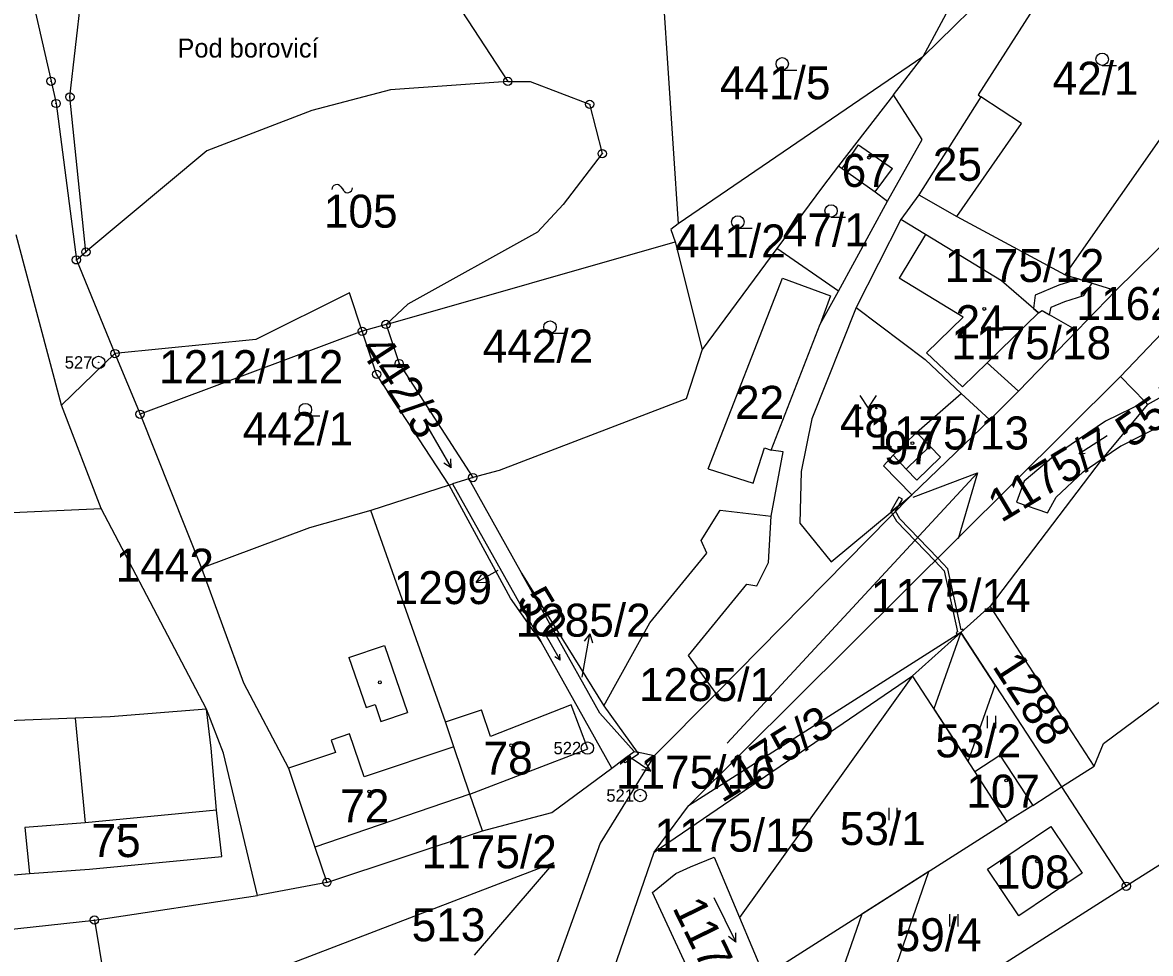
# Model space of a CAD drawing. Extents: x -564516 to -563466, y -1163913 to -1163170.
# Drawn here: x -564413.8 to -564277.2, y -1163494.9 to -1163382.1 of the extents above; entities that cross this region are included whole.
import ezdxf

# ---------------------------------------------------------------- set-up
doc = ezdxf.new("R2010")
doc.units = 0
for name, color, linetype in [('_ZOV', 7, 'Continuous'), ('Hranice parcel', 7, 'Continuous'), ('Parcelní čísla', 7, 'Continuous'), ('Pop  PČ popisy', 7, 'Continuous'), ('Vnitřní kresba', 7, 'Continuous'), ('Věcná břemena k části', 7, 'Continuous'), ('Značky bodu BP', 7, 'Continuous'), ('Značky budov', 7, 'Continuous'), ('Značky kultur', 7, 'Continuous')]:
    doc.layers.add(name, color=color, linetype=linetype)

msp = doc.modelspace()

# ---------------------------------------------------------------- linework, layer by layer
at = {"layer": '_ZOV'}
msp.add_line((-564328.48, -1163469.41), (-564298.18, -1163436.66), dxfattribs=at)
msp.add_lwpolyline([(-564305.96, -1163439.6), (-564298.18, -1163436.66), (-564300.5, -1163444.65)], dxfattribs=at)
at = {"layer": 'Hranice parcel'}
for p, q in [((-564287.56, -1163412.69), (-564255.92, -1163367.46)), ((-564299.02, -1163375.58), (-564304.77, -1163386.26)), ((-564336.38, -1163376.93), (-564334.4, -1163406.5)), ((-564304.77, -1163386.26), (-564334.4, -1163406.5)), ((-564308.34, -1163390.89), (-564304.77, -1163386.26)), ((-564308.34, -1163390.89), (-564315, -1163399.49)), ((-564297.75, -1163391.1), (-564305.26, -1163403.01)), ((-564281.4, -1163414.57), (-564257.3, -1163390.75)), ((-564314.98, -1163414.67), (-564309.04, -1163403.77)), ((-564305.26, -1163403.01), (-564307.45, -1163405.97)), ((-564305.26, -1163403.01), (-564300.68, -1163405.61)), ((-564307.45, -1163405.97), (-564312.84, -1163416.65)), ((-564300.68, -1163405.61), (-564287.56, -1163412.69)), ((-564409.08, -1163428.48), (-564414.56, -1163407.85)), ((-564369.77, -1163418.69), (-564334.77, -1163408.7)), ((-564334.77, -1163408.7), (-564331.48, -1163421.73)), ((-564322.46, -1163409.5), (-564331.48, -1163421.73)), ((-564314.98, -1163414.67), (-564322.46, -1163409.5)), ((-564407.26, -1163410.87), (-564406.11, -1163409.91)), ((-564407.26, -1163410.87), (-564402.59, -1163422.22)), ((-564287.56, -1163412.69), (-564281.4, -1163414.57)), ((-564269.44, -1163412.98), (-564280.83, -1163424.99)), ((-564372.65, -1163419.52), (-564374.19, -1163414.85)), ((-564281.4, -1163414.57), (-564286.09, -1163419.43)), ((-564367.13, -1163416.23), (-564369.77, -1163418.69)), ((-564369.77, -1163418.69), (-564372.65, -1163419.52)), ((-564372.65, -1163419.52), (-564399.56, -1163429.57)), ((-564286.09, -1163419.43), (-564293.19, -1163426.78)), ((-564409.08, -1163428.48), (-564402.59, -1163422.22)), ((-564402.59, -1163422.22), (-564399.56, -1163429.57)), ((-564333.17, -1163477.01), (-564280.83, -1163424.99)), ((-564280.83, -1163424.99), (-564277.87, -1163428.08)), ((-564305.53, -1163431.79), (-564300.13, -1163427.07)), ((-564300.13, -1163427.07), (-564296.65, -1163430.25)), ((-564296.65, -1163430.25), (-564293.19, -1163426.78)), ((-564277.59, -1163428.4), (-564275.38, -1163427.19)), ((-564404.27, -1163440.99), (-564409.08, -1163428.48)), ((-564277.59, -1163428.4), (-564283.08, -1163434.99)), ((-564277.87, -1163428.08), (-564282.66, -1163430.41)), ((-564277.87, -1163428.08), (-564277.59, -1163428.4)), ((-564399.56, -1163429.57), (-564392.13, -1163448.22)), ((-564296.65, -1163430.25), (-564306.13, -1163439.34)), ((-564305.53, -1163431.79), (-564308.38, -1163434.53)), ((-564280.8, -1163433.44), (-564283.08, -1163434.99)), ((-564283.08, -1163434.99), (-564296.64, -1163452.83)), ((-564285.36, -1163436.53), (-564283.08, -1163434.99)), ((-564362.14, -1163438.16), (-564371.62, -1163441.24)), ((-564362.14, -1163438.16), (-564361.71, -1163438.02)), ((-564359.75, -1163437.39), (-564361.71, -1163438.02)), ((-564361.71, -1163438.02), (-564351.01, -1163457.13)), ((-564359.27, -1163437.24), (-564359.75, -1163437.39)), ((-564359.75, -1163437.39), (-564353.36, -1163448.83)), ((-564306.13, -1163439.34), (-564329.81, -1163463.41)), ((-564463.39, -1163443.69), (-564404.27, -1163440.99)), ((-564391.49, -1163465.3), (-564404.27, -1163440.99)), ((-564353.36, -1163448.83), (-564343.41, -1163464.9)), ((-564296.64, -1163452.83), (-564300.18, -1163456.01)), ((-564284.03, -1163472.2), (-564296.64, -1163452.83)), ((-564300.18, -1163456.01), (-564333.17, -1163477.01)), ((-564306.04, -1163461.28), (-564300.18, -1163456.01)), ((-564300.18, -1163456.01), (-564287.99, -1163474.72)), ((-564342.44, -1163472.44), (-564351.01, -1163457.13)), ((-564337.31, -1163482.64), (-564306.04, -1163461.28)), ((-564306.04, -1163461.28), (-564326.97, -1163490.55)), ((-564298.48, -1163472.87), (-564306.04, -1163461.28)), ((-564282.89, -1163469.47), (-564271.83, -1163461.21)), ((-564329.81, -1163463.41), (-564337.3, -1163470.94)), ((-564343.41, -1163464.9), (-564339.38, -1163470.49)), ((-564284.03, -1163472.2), (-564282.89, -1163469.47)), ((-564341.11, -1163471.45), (-564339.72, -1163470.42)), ((-564339.2, -1163470.74), (-564340.83, -1163471.82)), ((-564339.72, -1163470.42), (-564339.38, -1163470.49)), ((-564337.3, -1163470.94), (-564339.38, -1163470.49)), ((-564339.38, -1163470.49), (-564339.2, -1163470.74)), ((-564342.44, -1163472.44), (-564341.11, -1163471.45)), ((-564340.83, -1163471.82), (-564341.11, -1163471.45)), ((-564287.99, -1163474.72), (-564284.03, -1163472.2)), ((-564294.55, -1163478.9), (-564298.48, -1163472.87)), ((-564291.48, -1163476.95), (-564287.99, -1163474.72)), ((-564287.99, -1163474.72), (-564280.15, -1163486.75)), ((-564337.31, -1163482.64), (-564333.17, -1163477.01)), ((-564291.48, -1163476.95), (-564294.55, -1163478.9)), ((-564323.98, -1163497.65), (-564294.55, -1163478.9)), ((-564376.94, -1163486.28), (-564358.11, -1163480.05)), ((-564347.82, -1163513.14), (-564337.31, -1163482.64)), ((-564330.06, -1163483.22), (-564326.97, -1163490.55)), ((-564274.36, -1163483.08), (-564280.15, -1163486.75)), ((-564412.93, -1163485.19), (-564405.68, -1163484.7)), ((-564429, -1163486.59), (-564412.93, -1163485.19)), ((-564376.94, -1163486.28), (-564385.35, -1163487.87)), ((-564280.15, -1163486.75), (-564304.67, -1163502.3)), ((-564405.08, -1163490.85), (-564385.35, -1163487.87)), ((-564332.5, -1163498.27), (-564337.51, -1163487.49)), ((-564405.08, -1163490.85), (-564403.85, -1163498.15)), ((-564326.97, -1163490.55), (-564323.98, -1163497.65))]:
    msp.add_line(p, q, dxfattribs=at)
for points in [[(-564304.77, -1163386.26), (-564295.23, -1163376.85), (-564283.56, -1163360.04), (-564247.75, -1163294.75)], [(-564375.89, -1163347.26), (-564386.66, -1163348.36), (-564392.67, -1163348.57), (-564397.72, -1163348.74), (-564404.66, -1163348.94), (-564419.03, -1163351.27), (-564410.33, -1163389.23), (-564409.72, -1163391.93), (-564407.26, -1163410.87)], [(-564406.11, -1163409.91), (-564408.05, -1163391.13), (-564406.67, -1163379.14), (-564401.67, -1163361.22), (-564394.92, -1163353.8), (-564383.29, -1163353.05), (-564374.57, -1163359.32), (-564355.03, -1163389.25)], [(-564274.65, -1163354.2), (-564298.1, -1163390.87), (-564297.75, -1163391.1)], [(-564355.03, -1163389.25), (-564369.22, -1163390.28), (-564378.74, -1163392.79), (-564391.47, -1163397.67), (-564406.11, -1163409.91)], [(-564355.03, -1163389.25), (-564352.34, -1163389.27), (-564345.12, -1163392.02), (-564343.6, -1163398), (-564348.33, -1163404.16), (-564351.45, -1163407.53), (-564367.13, -1163416.23)], [(-564309.04, -1163403.77), (-564304.87, -1163396.28), (-564308.34, -1163390.89)], [(-564300.68, -1163405.61), (-564292.84, -1163394.33), (-564297.75, -1163391.1)], [(-564315, -1163399.49), (-564316.94, -1163402.01), (-564322.46, -1163409.5)], [(-564315, -1163399.49), (-564314.55, -1163399.81), (-564310.57, -1163402.64), (-564309.04, -1163403.77)], [(-564334.4, -1163406.5), (-564335.29, -1163407.18), (-564334.77, -1163408.7)], [(-564290.77, -1163417.28), (-564295.26, -1163413.39), (-564304.44, -1163407.8), (-564307.45, -1163405.97)], [(-564374.19, -1163414.85), (-564385.53, -1163420.52), (-564402.59, -1163422.22)], [(-564323.13, -1163441.93), (-564321.68, -1163434.14), (-564323.16, -1163433.91), (-564317.21, -1163418.65), (-564314.98, -1163414.67)], [(-564312.84, -1163416.65), (-564318.21, -1163430.13), (-564319.52, -1163436.5), (-564319.69, -1163442.75), (-564315.89, -1163447.44), (-564306.13, -1163439.34)], [(-564312.84, -1163416.65), (-564304.48, -1163422.93), (-564300.13, -1163427.07)], [(-564293.19, -1163426.78), (-564296.98, -1163423.34), (-564290.77, -1163417.28)], [(-564290.77, -1163417.28), (-564290.33, -1163417), (-564286.09, -1163419.43)], [(-564369.77, -1163418.69), (-564368.18, -1163423.43), (-564359.27, -1163437.24)], [(-564362.14, -1163438.16), (-564370.91, -1163424.73), (-564372.65, -1163419.52)], [(-564331.48, -1163421.73), (-564333.44, -1163427.72), (-564356.08, -1163436.39), (-564359.27, -1163437.24)], [(-564266.24, -1163424.28), (-564275.15, -1163430.58), (-564280.8, -1163433.44)], [(-564282.66, -1163430.41), (-564288.94, -1163434.68), (-564292.52, -1163437.68), (-564293.42, -1163440.24), (-564289.69, -1163441.52), (-564288.64, -1163439.6), (-564285.36, -1163436.53)], [(-564308.38, -1163434.53), (-564306.81, -1163436.21), (-564305.52, -1163437.55), (-564302.65, -1163434.78), (-564303.94, -1163433.44), (-564305.53, -1163431.79)], [(-564306.13, -1163439.34), (-564309.54, -1163435.83), (-564308.38, -1163434.53)], [(-564351.01, -1163457.13), (-564354.7, -1163451.84), (-564362.14, -1163438.16)], [(-564371.62, -1163441.24), (-564379.02, -1163443.34), (-564392.13, -1163448.22)], [(-564358.11, -1163480.05), (-564359.63, -1163475.6), (-564361.55, -1163469.86), (-564362.57, -1163466.83), (-564371.62, -1163441.24)], [(-564343.41, -1163464.9), (-564337.83, -1163454.86), (-564330.94, -1163446.42), (-564331.62, -1163444.86), (-564329.33, -1163441.19), (-564323.13, -1163441.93)], [(-564329.81, -1163463.41), (-564333.15, -1163458.81), (-564326.08, -1163450.15), (-564324.88, -1163450.36), (-564323.47, -1163447.53), (-564323.13, -1163441.93)], [(-564392.13, -1163448.22), (-564387.04, -1163462.09), (-564381.6, -1163472.46), (-564378.4, -1163482.02), (-564376.94, -1163486.28)], [(-564339.72, -1163470.42), (-564343.9, -1163465.78), (-564353.36, -1163448.83)], [(-564391.49, -1163465.3), (-564403.17, -1163466.24), (-564407.43, -1163466.4)], [(-564405.68, -1163484.7), (-564389.65, -1163483.16), (-564390.28, -1163477.54), (-564390.95, -1163470.01), (-564391.49, -1163465.3)], [(-564385.35, -1163487.87), (-564389.44, -1163470.62), (-564391.49, -1163465.3)], [(-564407.43, -1163466.4), (-564414.53, -1163466.68), (-564430.16, -1163467.25)], [(-564407.43, -1163466.4), (-564406.22, -1163479.07), (-564413.51, -1163479.62), (-564412.93, -1163485.19)], [(-564337.3, -1163470.94), (-564343.85, -1163481.54), (-564352.25, -1163504.82), (-564360.15, -1163525.07)], [(-564298.48, -1163472.87), (-564295.46, -1163470.87), (-564291.48, -1163476.95)], [(-564358.11, -1163480.05), (-564349.68, -1163477.81), (-564342.44, -1163472.44)], [(-564289.29, -1163479.52), (-564285.5, -1163485.18), (-564293.17, -1163490.33), (-564296.94, -1163484.67), (-564289.29, -1163479.52)], [(-564337.51, -1163487.49), (-564334.69, -1163485.22), (-564332.93, -1163484.41), (-564330.06, -1163483.22)], [(-564359.05, -1163495.11), (-564349.44, -1163483.92), (-564380.93, -1163495.99)], [(-564516.35, -1163486.11), (-564490.44, -1163494.01), (-564475.97, -1163496.01), (-564456, -1163496.4), (-564405.08, -1163490.85)]]:
    msp.add_lwpolyline(points, dxfattribs=at)
at = {"layer": 'Pop  PČ popisy'}
for p, q in [((-564356.22, -1163448.5), (-564358.85, -1163449.96)), ((-564358.85, -1163449.96), (-564358.21, -1163449.03)), ((-564358.85, -1163449.96), (-564357.73, -1163449.91)), ((-564345.11, -1163456.19), (-564345.78, -1163457.08)), ((-564345.63, -1163459.14), (-564345.11, -1163456.19)), ((-564345.11, -1163456.19), (-564344.79, -1163457.26)), ((-564346.04, -1163461.41), (-564345.63, -1163459.14)), ((-564340.2, -1163471.13), (-564337.71, -1163472.81)), ((-564337.71, -1163472.81), (-564338.26, -1163471.83)), ((-564337.71, -1163472.81), (-564338.82, -1163472.66))]:
    msp.add_line(p, q, dxfattribs=at)
at = {"layer": 'Vnitřní kresba'}
for p, q in [((-564314.55, -1163399.81), (-564312.55, -1163396.94)), ((-564312.55, -1163396.94), (-564308.47, -1163399.79)), ((-564310.57, -1163402.64), (-564308.47, -1163399.79)), ((-564304.44, -1163407.8), (-564307.66, -1163413.1)), ((-564330.78, -1163436.17), (-564321.79, -1163413.09)), ((-564321.79, -1163413.09), (-564315.96, -1163415.21)), ((-564299.91, -1163417.82), (-564307.66, -1163413.1)), ((-564315.96, -1163415.21), (-564317.21, -1163418.65)), ((-564304.32, -1163422.12), (-564299.91, -1163417.82)), ((-564304.32, -1163422.12), (-564299.97, -1163426.26)), ((-564299.97, -1163426.26), (-564296.98, -1163423.34)), ((-564325.31, -1163437.92), (-564323.94, -1163433.66)), ((-564323.94, -1163433.66), (-564323.16, -1163433.91)), ((-564306.81, -1163436.21), (-564303.94, -1163433.44)), ((-564330.78, -1163436.17), (-564325.31, -1163437.92)), ((-564374.26, -1163459.04), (-564369.96, -1163457.57)), ((-564369.96, -1163457.57), (-564367.17, -1163465.71)), ((-564374.26, -1163459.04), (-564372.19, -1163465.1)), ((-564372.19, -1163465.1), (-564371.1, -1163464.73)), ((-564371.1, -1163464.73), (-564370.39, -1163466.81)), ((-564362.57, -1163466.83), (-564358.21, -1163465.36)), ((-564357.12, -1163468.6), (-564358.21, -1163465.36)), ((-564347.35, -1163464.76), (-564357.12, -1163468.6)), ((-564345.34, -1163470.12), (-564347.35, -1163464.76)), ((-564370.39, -1163466.81), (-564367.17, -1163465.71)), ((-564374.19, -1163468.29), (-564376.42, -1163469.04)), ((-564372.44, -1163473.51), (-564374.19, -1163468.29)), ((-564376.42, -1163469.04), (-564375.91, -1163470.55)), ((-564375.91, -1163470.55), (-564381.6, -1163472.46)), ((-564361.55, -1163469.86), (-564372.44, -1163473.51)), ((-564359.63, -1163475.6), (-564345.34, -1163470.12)), ((-564359.63, -1163475.6), (-564378.4, -1163482.02)), ((-564390.28, -1163477.54), (-564406.22, -1163479.07))]:
    msp.add_line(p, q, dxfattribs=at)
at = {"layer": 'Věcná břemena k části'}
for points in [[(-564288.31, -1163413.95), (-564291.18, -1163415.14), (-564291.37, -1163416.76), (-564290.77, -1163417.28), (-564290.33, -1163417), (-564289.45, -1163417.51), (-564289.23, -1163416.61), (-564287.57, -1163415.93), (-564285.29, -1163415.18), (-564284.28, -1163413.69), (-564286.39, -1163413.05), (-564286.63, -1163413.4)], [(-564307.7, -1163439.62), (-564308.65, -1163441.31), (-564308.6, -1163441.39), (-564307.69, -1163440.64), (-564307.26, -1163439.86)], [(-564301.74, -1163448.29), (-564302.98, -1163447), (-564307.56, -1163442.24), (-564308.08, -1163441.32), (-564307.69, -1163440.64), (-564308.6, -1163441.39), (-564308.44, -1163441.69), (-564307.96, -1163442.54), (-564303.33, -1163447.35), (-564302.2, -1163448.53), (-564300.58, -1163455.94), (-564300.75, -1163456.03), (-564300.61, -1163456.29), (-564300.18, -1163456.01), (-564299.88, -1163455.74), (-564299.95, -1163455.61), (-564300.12, -1163455.7)], [(-564296.03, -1163462.38), (-564300.18, -1163456.01), (-564303.44, -1163465.27), (-564299.29, -1163471.63)], [(-564311.37, -1163506.14), (-564304.06, -1163484.96), (-564312.18, -1163490.13), (-564318.94, -1163509.62), (-564318.65, -1163510.3)]]:
    msp.add_lwpolyline(points, close=True, dxfattribs=at)
at = {"layer": 'Značky bodu BP'}
for centre, radius in [((-564410.33, -1163389.23), 0.5), ((-564355.03, -1163389.25), 0.5), ((-564410.33, -1163389.23), 0.0303), ((-564355.03, -1163389.25), 0.0303), ((-564409.72, -1163391.93), 0.5), ((-564408.05, -1163391.13), 0.5), ((-564408.05, -1163391.13), 0.0303), ((-564345.12, -1163392.02), 0.5), ((-564409.72, -1163391.93), 0.0303), ((-564345.12, -1163392.02), 0.0303), ((-564343.6, -1163398), 0.5), ((-564343.6, -1163398), 0.0303), ((-564406.11, -1163409.91), 0.5), ((-564407.26, -1163410.87), 0.5), ((-564407.26, -1163410.87), 0.0303), ((-564406.11, -1163409.91), 0.0303), ((-564372.65, -1163419.52), 0.5), ((-564369.77, -1163418.69), 0.5), ((-564369.77, -1163418.69), 0.0303), ((-564372.65, -1163419.52), 0.0303), ((-564402.59, -1163422.22), 0.5), ((-564404.57, -1163423.29), 0.75), ((-564404.57, -1163423.29), 0.03), ((-564402.59, -1163422.22), 0.0303), ((-564368.18, -1163423.43), 0.5), ((-564370.91, -1163424.73), 0.5), ((-564368.18, -1163423.43), 0.0303), ((-564370.91, -1163424.73), 0.0303), ((-564399.56, -1163429.57), 0.5), ((-564399.56, -1163429.57), 0.0303), ((-564359.27, -1163437.24), 0.5), ((-564359.27, -1163437.24), 0.0303), ((-564345.39, -1163470.01), 0.75), ((-564345.39, -1163470.01), 0.03), ((-564339, -1163475.76), 0.75), ((-564339, -1163475.76), 0.03), ((-564376.94, -1163486.28), 0.5), ((-564376.94, -1163486.28), 0.0303), ((-564280.15, -1163486.75), 0.5), ((-564280.15, -1163486.75), 0.0303), ((-564405.08, -1163490.85), 0.5), ((-564405.08, -1163490.85), 0.0303)]:
    msp.add_circle(centre, radius, dxfattribs=at)
at = {"layer": 'Značky budov'}
msp.add_line((-564375.24, -1163402.04), (-564374.94, -1163402.44), dxfattribs=at)
for centre in [(-564311.29, -1163398.48), (-564300.03, -1163397.74), (-564297.34, -1163416.81), (-564323.94, -1163426.58), (-564306.04, -1163433.07), (-564370.53, -1163462.05), (-564354.62, -1163469.68), (-564294.69, -1163473.94), (-564371.81, -1163475.27), (-564402.04, -1163479.67), (-564290.95, -1163483.72)]:
    msp.add_circle(centre, 0.175, dxfattribs=at)
for centre, start, end in [((-564375.75, -1163402.33), 29.2914, 181.2189), ((-564374.43, -1163402.15), 209.2914, 1.2189)]:
    msp.add_arc(centre, 0.588, start, end, dxfattribs=at)
at = {"layer": 'Značky kultur'}
for p, q in [((-564283.07, -1163387.32), (-564281.32, -1163387.32)), ((-564321.8, -1163387.87), (-564320.05, -1163387.87)), ((-564315.89, -1163405.69), (-564314.14, -1163405.69)), ((-564327.18, -1163407.03), (-564325.43, -1163407.03)), ((-564349.92, -1163419.76), (-564348.17, -1163419.76)), ((-564379.54, -1163429.77), (-564377.79, -1163429.77)), ((-564364.87, -1163430.88), (-564361.87, -1163436.08)), ((-564282.47, -1163432.19), (-564285.84, -1163434.38)), ((-564285.84, -1163434.38), (-564285.47, -1163433.74)), ((-564361.87, -1163436.08), (-564362.79, -1163435.48)), ((-564361.87, -1163436.08), (-564361.92, -1163434.98)), ((-564285.84, -1163434.38), (-564285.11, -1163434.3)), ((-564350.72, -1163455.87), (-564348.71, -1163459.35)), ((-564348.71, -1163459.35), (-564348.75, -1163458.62)), ((-564348.71, -1163459.35), (-564349.33, -1163458.96)), ((-564296.95, -1163467.59), (-564296.95, -1163466.09)), ((-564295.95, -1163467.59), (-564295.95, -1163466.09)), ((-564308.87, -1163478.76), (-564308.87, -1163477.26)), ((-564307.87, -1163478.76), (-564307.87, -1163477.26)), ((-564330.07, -1163488.11), (-564327.44, -1163493.51)), ((-564301.51, -1163491.62), (-564301.51, -1163490.12)), ((-564300.51, -1163491.62), (-564300.51, -1163490.12)), ((-564327.44, -1163493.51), (-564328.31, -1163492.85)), ((-564327.44, -1163493.51), (-564327.41, -1163492.41))]:
    msp.add_line(p, q, dxfattribs=at)
msp.add_lwpolyline([(-564312.41, -1163427.32), (-564311.41, -1163428.82), (-564310.41, -1163427.32)], dxfattribs=at)
for centre, radius in [((-564321.8, -1163387.12), 0.75), ((-564283.07, -1163386.57), 0.75), ((-564315.89, -1163404.94), 0.75), ((-564327.18, -1163406.28), 0.75), ((-564349.92, -1163419.01), 0.75), ((-564379.54, -1163429.02), 0.75), ((-564312.41, -1163428.82), 0.1), ((-564310.41, -1163428.82), 0.1)]:
    msp.add_circle(centre, radius, dxfattribs=at)

# ---------------------------------------------------------------- texts
at = {"layer": 'Parcelní čísla'}
for s, p in [('441/5', (-564329.35, -1163391.42)), ('42/1', (-564289.07, -1163390.87)), ('25', (-564303.57, -1163401.29)), ('67', (-564314.61, -1163402.03)), ('105', (-564377.3, -1163406.97)), ('47/1', (-564321.74, -1163409.24)), ('441/2', (-564334.76, -1163410.58)), ('1175/12', (-564302.14, -1163413.55)), ('1162/1', (-564286.18, -1163418.16)), ('24', (-564300.82, -1163420.36)), ('442/2', (-564358.07, -1163423.31)), ('1175/18', (-564301.32, -1163422.92)), ('1212/112', (-564397.25, -1163425.81)), ('22', (-564327.52, -1163430.13)), ('48', (-564314.82, -1163432.37)), ('442/1', (-564387.12, -1163433.32)), ('1175/13', (-564311.25, -1163433.84)), ('97', (-564309.5, -1163435.63)), ('1442', (-564402.51, -1163449.86)), ('1299', (-564368.84, -1163452.57)), ('1175/14', (-564311.07, -1163453.53)), ('1285/2', (-564354.09, -1163456.52)), ('1285/1', (-564339.15, -1163464.32)), ('53/2', (-564303.27, -1163471.14)), ('78', (-564357.97, -1163473.23)), ('1175/16', (-564341.94, -1163474.93)), ('107', (-564299.52, -1163477.23)), ('72', (-564375.32, -1163479.02)), ('53/1', (-564314.84, -1163481.76)), ('75', (-564405.43, -1163483.22)), ('1175/15', (-564337.27, -1163482.56)), ('1175/2', (-564365.46, -1163484.58)), ('108', (-564295.95, -1163487.03)), ('513', (-564366.67, -1163493.42)), ('59/4', (-564308.08, -1163494.62))]:
    msp.add_text(s, height=4, dxfattribs=at).set_placement(p)
for s, rotation, p in [('442/3', 303, (-564373.08, -1163421.65)), ('55/2', 35, (-564279.6, -1163433.79)), ('1175/7', 31, (-564295.3, -1163442.77)), ('50', 301, (-564354.07, -1163452.05)), ('1288', 303, (-564296.45, -1163460.1)), ('1175/3', 32, (-564329.09, -1163476.7)), ('1175/17', 296, (-564335.16, -1163489.33))]:
    msp.add_text(s, height=4, rotation=rotation, dxfattribs=at).set_placement(p)
at = {"layer": 'Pop  PČ popisy'}
msp.add_text('Pod borovicí', height=2.3, dxfattribs=at).set_placement((-564395.03, -1163386.36))
at = {"layer": 'Značky bodu BP'}
for s, p in [('527', (-564408.67, -1163424.04)), ('522', (-564349.49, -1163470.76)), ('521', (-564343.1, -1163476.51))]:
    msp.add_text(s, height=1.5, dxfattribs=at).set_placement(p)

doc.saveas('drawing.dxf')
